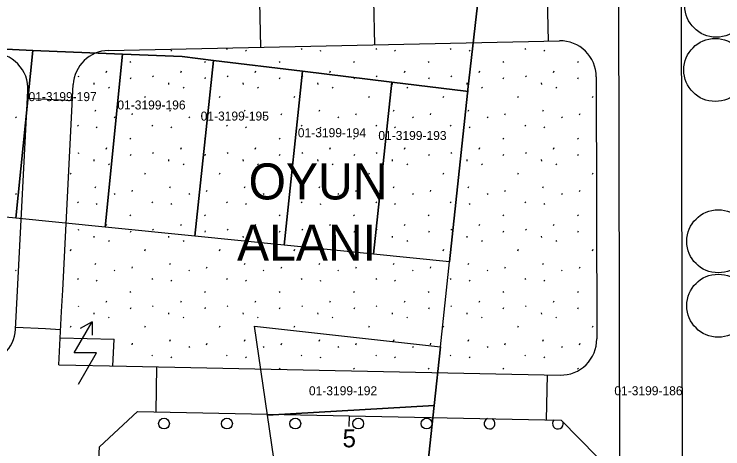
# Model space of a CAD drawing. Extents: x 419396 to 421519, y 4453567 to 4456767.
# Drawn here: x 420471.1 to 420549.9, y 4454570.9 to 4454619.2 of the extents above; entities that cross this region are included whole.
import ezdxf

# ---------------------------------------------------------------- set-up
doc = ezdxf.new("R2010")
doc.units = 0
for name, color, linetype in [('0_KADASTRO', 7, 'Continuous'), ('Level 20', 7, 'Continuous'), ('Level 28', 7, 'Continuous'), ('Level 29', 7, 'Continuous'), ('Level 33', 7, 'Continuous'), ('Level 41', 7, 'Continuous'), ('Level 54', 7, 'Continuous'), ('Level 55', 7, 'Continuous'), ('Level 57', 7, 'Continuous'), ('Level 61', 7, 'Continuous'), ('Level 62', 7, 'Continuous')]:
    doc.layers.add(name, color=color, linetype=linetype)

msp = doc.modelspace()

# ---------------------------------------------------------------- linework, layer by layer
at = {"layer": '0_KADASTRO'}
for points in [[(420411.106, 4454610.555), (420417.99, 4454723.39), (420418.06, 4454727.12), (420520.79, 4454737.14), (420523.08, 4454624.123), (420522.64, 4454620.22), (420521.583, 4454610.83), (420521.558, 4454610.634), (420521.36, 4454610.658), (420513.123, 4454611.658), (420503.201, 4454612.866), (420493.288, 4454614.075), (420489.81, 4454614.5), (420483.17, 4454614.78), (420473.19, 4454615.195), (420469.384, 4454615.353), (420447.99, 4454608.07), (420428.468, 4454594.055), (420413.06, 4454586.21), (420411.13, 4454609.71)], [(420515.046, 4454549.714), (420515.807, 4454556.873), (420516.899, 4454567.106), (420517.826, 4454575.752), (420518.521, 4454582.262), (420519.54, 4454591.714), (420521.536, 4454610.43), (420521.558, 4454610.634), (420521.583, 4454610.83), (420522.64, 4454620.22), (420523.08, 4454624.123), (420581.08, 4454632.15), (420580.07, 4454615.58), (420569.14, 4454565.51), (420569.77, 4454541.42), (420572.69, 4454525.26), (420529.64, 4454525.09), (420525.79, 4454524.02), (420524.53, 4454527.02), (420520.228, 4454537.319), (420516.246, 4454546.834)], [(420461.37, 4454597.533), (420462.84, 4454612.64), (420469.384, 4454615.353), (420473.19, 4454615.195), (420471.314, 4454596.544)], [(420471.314, 4454596.544), (420473.19, 4454615.195), (420483.17, 4454614.78), (420481.249, 4454595.545)], [(420481.249, 4454595.545), (420483.17, 4454614.78), (420489.81, 4454614.5), (420493.288, 4454614.075), (420491.194, 4454594.546)], [(420491.194, 4454594.546), (420493.288, 4454614.075), (420503.201, 4454612.866), (420501.138, 4454593.557)], [(420501.138, 4454593.557), (420503.201, 4454612.866), (420513.123, 4454611.658), (420511.083, 4454592.558)], [(420511.083, 4454592.558), (420513.123, 4454611.658), (420521.36, 4454610.658), (420521.558, 4454610.634), (420521.536, 4454610.43), (420519.54, 4454591.714)], [(420497.855, 4454584.548), (420518.521, 4454582.262), (420517.826, 4454575.752), (420499.295, 4454574.659)], [(420499.295, 4454574.659), (420517.826, 4454575.752), (420516.899, 4454567.106), (420500.744, 4454564.77)]]:
    msp.add_lwpolyline(points, close=True, dxfattribs=at)
at = {"layer": 'Level 20'}
msp.add_line((420508.359, 4454574.599), (420508.335, 4454573.4), dxfattribs=at)
at = {"layer": 'Level 28'}
for p, q in [((420530.525, 4454616.225), (420530.418, 4454621.224)), ((420498.388, 4454620.541), (420498.495, 4454615.542)), ((420511.084, 4454620.812), (420511.191, 4454615.813)), ((420481.608, 4454615.182), (420531.757, 4454616.251)), ((420535.842, 4454612.262), (420535.909, 4454583.133)), ((420476.516, 4454588.55), (420477.699, 4454611.39)), ((420471.507, 4454588.489), (420472.656, 4454610.699)), ((420472.615, 4454609.893), (420477.608, 4454609.634)), ((420471.286, 4454584.224), (420471.507, 4454588.489)), ((420476.393, 4454586.171), (420476.516, 4454588.55)), ((420476.516, 4454588.55), (420476.516, 4454588.55)), ((420476.087, 4454580.252), (420476.393, 4454586.171)), ((420476.393, 4454586.171), (420476.393, 4454586.171)), ((420471.297, 4454584.451), (420474.593, 4454584.281)), ((420474.593, 4454584.281), (420474.593, 4454584.281)), ((420474.593, 4454584.281), (420476.291, 4454584.193)), ((420476.087, 4454580.252), (420483.626, 4454580.1)), ((420483.626, 4454580.1), (420531.829, 4454579.125)), ((420486.9, 4454575.033), (420487.001, 4454580.032)), ((420530.317, 4454574.154), (420530.418, 4454579.153))]:
    msp.add_line(p, q, dxfattribs=at)
for centre, start, end in [((420531.842, 4454612.252), 0.13291, 91.22124), ((420481.693, 4454611.183), 91.22124, 177.03634), ((420468.662, 4454610.905), 357.03634, 91.22124), ((420467.291, 4454584.431), 268.8411, 357.03634), ((420531.909, 4454583.124), 268.8411, 0.13291)]:
    msp.add_arc(centre, 4, start, end, dxfattribs=at)
at = {"layer": 'Level 29'}
for p, q in [((420480.623, 4454571.161), (420484.829, 4454575.075)), ((420484.829, 4454575.075), (420531.931, 4454574.122)), ((420531.931, 4454574.122), (420535.94, 4454570.041)), ((420478.347, 4454527.194), (420480.623, 4454571.161))]:
    msp.add_line(p, q, dxfattribs=at)
at = {"layer": 'Level 33'}
for centre in [(420487.783, 4454573.735), (420494.783, 4454573.735), (420502.383, 4454573.735), (420509.383, 4454573.735), (420516.983, 4454573.735)]:
    msp.add_circle(centre, 0.6, dxfattribs=at)
for centre, start, end in [((420523.983, 4454573.735), 112.86595, 64.81587), ((420531.583, 4454573.735), 137.75884, 14.62376)]:
    msp.add_arc(centre, 0.6, start, end, dxfattribs=at)
at = {"layer": 'Level 41'}
for p, q in [((420532.059, 4454616.228), (420532.068, 4454616.216)), ((420486.517, 4454615.288), (420486.518, 4454615.286)), ((420488.546, 4454615.201), (420488.617, 4454615.094)), ((420494.74, 4454615.393), (420494.811, 4454615.286)), ((420496.839, 4454615.201), (420496.91, 4454615.094)), ((420503.033, 4454615.393), (420503.104, 4454615.286)), ((420505.132, 4454615.201), (420505.203, 4454615.094)), ((420511.326, 4454615.393), (420511.397, 4454615.286)), ((420513.425, 4454615.201), (420513.496, 4454615.094)), ((420519.619, 4454615.393), (420519.69, 4454615.286)), ((420521.718, 4454615.201), (420521.789, 4454615.094)), ((420527.912, 4454615.393), (420527.983, 4454615.286)), ((420530.011, 4454615.201), (420530.082, 4454615.094)), ((420483.991, 4454613.94), (420484.062, 4454613.833)), ((420492.284, 4454613.94), (420492.355, 4454613.833)), ((420500.577, 4454613.94), (420500.648, 4454613.833)), ((420508.87, 4454613.94), (420508.941, 4454613.833)), ((420517.163, 4454613.94), (420517.234, 4454613.833)), ((420525.456, 4454613.94), (420525.527, 4454613.833)), ((420533.749, 4454613.94), (420533.82, 4454613.833)), ((420481.35, 4454612.747), (420481.421, 4454612.906)), ((420489.643, 4454612.747), (420489.714, 4454612.906)), ((420497.936, 4454612.747), (420498.007, 4454612.906)), ((420506.229, 4454612.747), (420506.3, 4454612.906)), ((420514.522, 4454612.747), (420514.593, 4454612.906)), ((420522.815, 4454612.747), (420522.886, 4454612.906)), ((420531.108, 4454612.747), (420531.179, 4454612.906)), ((420478.221, 4454612.363), (420478.292, 4454612.256)), ((420484.049, 4454612.018), (420484.121, 4454612.178)), ((420486.514, 4454612.363), (420486.585, 4454612.256)), ((420492.342, 4454612.018), (420492.414, 4454612.178)), ((420494.807, 4454612.363), (420494.878, 4454612.256)), ((420500.635, 4454612.018), (420500.707, 4454612.178)), ((420503.1, 4454612.363), (420503.171, 4454612.256)), ((420508.928, 4454612.018), (420509, 4454612.178)), ((420511.393, 4454612.363), (420511.464, 4454612.256)), ((420517.221, 4454612.018), (420517.293, 4454612.178)), ((420519.686, 4454612.363), (420519.757, 4454612.256)), ((420525.514, 4454612.018), (420525.586, 4454612.178)), ((420527.979, 4454612.363), (420528.05, 4454612.256)), ((420533.807, 4454612.018), (420533.879, 4454612.178)), ((420479.979, 4454611.572), (420479.997, 4454611.412)), ((420481.609, 4454611.102), (420481.679, 4454610.995)), ((420488.272, 4454611.572), (420488.29, 4454611.412)), ((420489.902, 4454611.102), (420489.972, 4454610.995)), ((420496.565, 4454611.572), (420496.583, 4454611.412)), ((420498.195, 4454611.102), (420498.265, 4454610.995)), ((420504.858, 4454611.572), (420504.876, 4454611.412)), ((420506.488, 4454611.102), (420506.558, 4454610.995)), ((420513.151, 4454611.572), (420513.169, 4454611.412)), ((420514.781, 4454611.102), (420514.851, 4454610.995)), ((420521.444, 4454611.572), (420521.462, 4454611.412)), ((420523.074, 4454611.102), (420523.144, 4454610.995)), ((420529.737, 4454611.572), (420529.755, 4454611.412)), ((420531.367, 4454611.102), (420531.437, 4454610.995)), ((420485.665, 4454609.958), (420485.737, 4454610.118)), ((420493.958, 4454609.958), (420494.03, 4454610.118)), ((420502.251, 4454609.958), (420502.323, 4454610.118)), ((420510.544, 4454609.958), (420510.616, 4454610.118)), ((420518.837, 4454609.958), (420518.909, 4454610.118)), ((420527.13, 4454609.958), (420527.202, 4454610.118)), ((420535.423, 4454609.958), (420535.495, 4454610.118)), ((420480.144, 4454608.428), (420480.214, 4454608.588)), ((420484.227, 4454608.02), (420484.298, 4454608.18)), ((420488.437, 4454608.428), (420488.507, 4454608.588)), ((420492.52, 4454608.02), (420492.591, 4454608.18)), ((420496.73, 4454608.428), (420496.8, 4454608.588)), ((420500.813, 4454608.02), (420500.884, 4454608.18)), ((420505.023, 4454608.428), (420505.093, 4454608.588)), ((420509.106, 4454608.02), (420509.177, 4454608.18)), ((420513.316, 4454608.428), (420513.386, 4454608.588)), ((420517.399, 4454608.02), (420517.47, 4454608.18)), ((420521.609, 4454608.428), (420521.679, 4454608.588)), ((420525.692, 4454608.02), (420525.763, 4454608.18)), ((420529.902, 4454608.428), (420529.972, 4454608.588)), ((420533.985, 4454608.02), (420534.056, 4454608.18)), ((420471.263, 4454607.812), (420471.334, 4454607.706)), ((420482.239, 4454607.812), (420482.31, 4454607.706)), ((420490.532, 4454607.812), (420490.603, 4454607.706)), ((420498.825, 4454607.812), (420498.896, 4454607.706)), ((420507.118, 4454607.812), (420507.189, 4454607.706)), ((420515.411, 4454607.812), (420515.482, 4454607.706)), ((420523.704, 4454607.812), (420523.775, 4454607.706)), ((420531.997, 4454607.812), (420532.068, 4454607.706)), ((420478.154, 4454606.883), (420478.225, 4454606.776)), ((420480.253, 4454606.691), (420480.324, 4454606.584)), ((420486.447, 4454606.883), (420486.518, 4454606.776)), ((420488.546, 4454606.691), (420488.617, 4454606.584)), ((420494.74, 4454606.883), (420494.811, 4454606.776)), ((420496.839, 4454606.691), (420496.91, 4454606.584)), ((420503.033, 4454606.883), (420503.104, 4454606.776)), ((420505.132, 4454606.691), (420505.203, 4454606.584)), ((420511.326, 4454606.883), (420511.397, 4454606.776)), ((420513.425, 4454606.691), (420513.496, 4454606.584)), ((420519.619, 4454606.883), (420519.69, 4454606.776)), ((420521.718, 4454606.691), (420521.789, 4454606.584)), ((420527.912, 4454606.883), (420527.983, 4454606.776)), ((420530.011, 4454606.691), (420530.082, 4454606.584)), ((420483.991, 4454605.43), (420484.062, 4454605.323)), ((420492.284, 4454605.43), (420492.355, 4454605.323)), ((420500.577, 4454605.43), (420500.648, 4454605.323)), ((420508.87, 4454605.43), (420508.941, 4454605.323)), ((420517.163, 4454605.43), (420517.234, 4454605.323)), ((420525.456, 4454605.43), (420525.527, 4454605.323)), ((420533.749, 4454605.43), (420533.82, 4454605.323)), ((420481.35, 4454604.237), (420481.421, 4454604.396)), ((420489.643, 4454604.237), (420489.714, 4454604.396)), ((420497.936, 4454604.237), (420498.007, 4454604.396)), ((420506.229, 4454604.237), (420506.3, 4454604.396)), ((420514.522, 4454604.237), (420514.593, 4454604.396)), ((420522.815, 4454604.237), (420522.886, 4454604.396)), ((420531.108, 4454604.237), (420531.179, 4454604.396)), ((420478.221, 4454603.853), (420478.292, 4454603.746)), ((420484.049, 4454603.508), (420484.121, 4454603.668)), ((420486.514, 4454603.853), (420486.585, 4454603.746)), ((420492.342, 4454603.508), (420492.414, 4454603.668)), ((420494.807, 4454603.853), (420494.878, 4454603.746)), ((420500.635, 4454603.508), (420500.707, 4454603.668)), ((420503.1, 4454603.853), (420503.171, 4454603.746)), ((420508.928, 4454603.508), (420509, 4454603.668)), ((420511.393, 4454603.853), (420511.464, 4454603.746)), ((420517.221, 4454603.508), (420517.293, 4454603.668)), ((420519.686, 4454603.853), (420519.757, 4454603.746)), ((420525.514, 4454603.508), (420525.586, 4454603.668)), ((420527.979, 4454603.853), (420528.05, 4454603.746)), ((420533.807, 4454603.508), (420533.879, 4454603.668)), ((420479.979, 4454603.062), (420479.997, 4454602.902)), ((420481.609, 4454602.592), (420481.679, 4454602.485)), ((420488.272, 4454603.062), (420488.29, 4454602.902)), ((420489.902, 4454602.592), (420489.972, 4454602.485)), ((420496.565, 4454603.062), (420496.583, 4454602.902)), ((420498.195, 4454602.592), (420498.265, 4454602.485)), ((420504.858, 4454603.062), (420504.876, 4454602.902)), ((420506.488, 4454602.592), (420506.558, 4454602.485)), ((420513.151, 4454603.062), (420513.169, 4454602.902)), ((420514.781, 4454602.592), (420514.851, 4454602.485)), ((420521.444, 4454603.062), (420521.462, 4454602.902)), ((420523.074, 4454602.592), (420523.144, 4454602.485)), ((420529.737, 4454603.062), (420529.755, 4454602.902)), ((420531.367, 4454602.592), (420531.437, 4454602.485)), ((420477.372, 4454601.448), (420477.444, 4454601.608)), ((420485.665, 4454601.448), (420485.737, 4454601.608)), ((420493.958, 4454601.448), (420494.03, 4454601.608)), ((420502.251, 4454601.448), (420502.323, 4454601.608)), ((420510.544, 4454601.448), (420510.616, 4454601.608)), ((420518.837, 4454601.448), (420518.909, 4454601.608)), ((420527.13, 4454601.448), (420527.202, 4454601.608)), ((420535.423, 4454601.448), (420535.495, 4454601.608)), ((420480.144, 4454599.918), (420480.214, 4454600.078)), ((420488.437, 4454599.918), (420488.507, 4454600.078)), ((420496.73, 4454599.918), (420496.8, 4454600.078)), ((420505.023, 4454599.918), (420505.093, 4454600.078)), ((420513.316, 4454599.918), (420513.386, 4454600.078)), ((420521.609, 4454599.918), (420521.679, 4454600.078)), ((420529.902, 4454599.918), (420529.972, 4454600.078)), ((420471.263, 4454599.302), (420471.334, 4454599.196)), ((420482.239, 4454599.302), (420482.31, 4454599.196)), ((420484.227, 4454599.51), (420484.298, 4454599.67)), ((420490.532, 4454599.302), (420490.603, 4454599.196)), ((420492.52, 4454599.51), (420492.591, 4454599.67)), ((420498.825, 4454599.302), (420498.896, 4454599.196)), ((420500.813, 4454599.51), (420500.884, 4454599.67)), ((420507.118, 4454599.302), (420507.189, 4454599.196)), ((420509.106, 4454599.51), (420509.177, 4454599.67)), ((420515.411, 4454599.302), (420515.482, 4454599.196)), ((420517.399, 4454599.51), (420517.47, 4454599.67)), ((420523.704, 4454599.302), (420523.775, 4454599.196)), ((420525.692, 4454599.51), (420525.763, 4454599.67)), ((420531.997, 4454599.302), (420532.068, 4454599.196)), ((420533.985, 4454599.51), (420534.056, 4454599.67)), ((420478.154, 4454598.373), (420478.225, 4454598.266)), ((420486.447, 4454598.373), (420486.518, 4454598.266)), ((420494.74, 4454598.373), (420494.811, 4454598.266)), ((420503.033, 4454598.373), (420503.104, 4454598.266)), ((420511.326, 4454598.373), (420511.397, 4454598.266)), ((420519.619, 4454598.373), (420519.69, 4454598.266)), ((420527.912, 4454598.373), (420527.983, 4454598.266)), ((420480.253, 4454598.181), (420480.324, 4454598.074)), ((420488.546, 4454598.181), (420488.617, 4454598.074)), ((420496.839, 4454598.181), (420496.91, 4454598.074)), ((420505.132, 4454598.181), (420505.203, 4454598.074)), ((420513.425, 4454598.181), (420513.496, 4454598.074)), ((420521.718, 4454598.181), (420521.789, 4454598.074)), ((420530.011, 4454598.181), (420530.082, 4454598.074)), ((420483.991, 4454596.92), (420484.062, 4454596.813)), ((420492.284, 4454596.92), (420492.355, 4454596.813)), ((420500.577, 4454596.92), (420500.648, 4454596.813)), ((420508.87, 4454596.92), (420508.941, 4454596.813)), ((420517.163, 4454596.92), (420517.234, 4454596.813)), ((420525.456, 4454596.92), (420525.527, 4454596.813)), ((420533.749, 4454596.92), (420533.82, 4454596.813)), ((420478.221, 4454595.343), (420478.292, 4454595.236)), ((420481.35, 4454595.727), (420481.421, 4454595.886)), ((420486.514, 4454595.343), (420486.585, 4454595.236)), ((420489.643, 4454595.727), (420489.714, 4454595.886)), ((420494.807, 4454595.343), (420494.878, 4454595.236)), ((420497.936, 4454595.727), (420498.007, 4454595.886)), ((420503.1, 4454595.343), (420503.171, 4454595.236)), ((420506.229, 4454595.727), (420506.3, 4454595.886)), ((420511.393, 4454595.343), (420511.464, 4454595.236)), ((420514.522, 4454595.727), (420514.593, 4454595.886)), ((420519.686, 4454595.343), (420519.757, 4454595.236)), ((420522.815, 4454595.727), (420522.886, 4454595.886)), ((420527.979, 4454595.343), (420528.05, 4454595.236)), ((420531.108, 4454595.727), (420531.179, 4454595.886)), ((420479.979, 4454594.552), (420479.997, 4454594.392)), ((420484.049, 4454594.998), (420484.121, 4454595.158)), ((420488.272, 4454594.552), (420488.29, 4454594.392)), ((420492.342, 4454594.998), (420492.414, 4454595.158)), ((420496.565, 4454594.552), (420496.583, 4454594.392)), ((420500.635, 4454594.998), (420500.707, 4454595.158)), ((420504.858, 4454594.552), (420504.876, 4454594.392)), ((420508.928, 4454594.998), (420509, 4454595.158)), ((420513.151, 4454594.552), (420513.169, 4454594.392)), ((420517.221, 4454594.998), (420517.293, 4454595.158)), ((420521.444, 4454594.552), (420521.462, 4454594.392)), ((420525.514, 4454594.998), (420525.586, 4454595.158)), ((420529.737, 4454594.552), (420529.755, 4454594.392)), ((420533.807, 4454594.998), (420533.879, 4454595.158)), ((420481.609, 4454594.082), (420481.679, 4454593.975)), ((420489.902, 4454594.082), (420489.972, 4454593.975)), ((420498.195, 4454594.082), (420498.265, 4454593.975)), ((420506.488, 4454594.082), (420506.558, 4454593.975)), ((420514.781, 4454594.082), (420514.851, 4454593.975)), ((420523.074, 4454594.082), (420523.144, 4454593.975)), ((420531.367, 4454594.082), (420531.437, 4454593.975)), ((420477.372, 4454592.938), (420477.444, 4454593.098)), ((420485.665, 4454592.938), (420485.737, 4454593.098)), ((420493.958, 4454592.938), (420494.03, 4454593.098)), ((420502.251, 4454592.938), (420502.323, 4454593.098)), ((420510.544, 4454592.938), (420510.616, 4454593.098)), ((420518.837, 4454592.938), (420518.909, 4454593.098)), ((420527.13, 4454592.938), (420527.202, 4454593.098)), ((420535.423, 4454592.938), (420535.495, 4454593.098)), ((420480.144, 4454591.408), (420480.214, 4454591.568)), ((420488.437, 4454591.408), (420488.507, 4454591.568)), ((420496.73, 4454591.408), (420496.8, 4454591.568)), ((420505.023, 4454591.408), (420505.093, 4454591.568)), ((420513.316, 4454591.408), (420513.386, 4454591.568)), ((420521.609, 4454591.408), (420521.679, 4454591.568)), ((420529.902, 4454591.408), (420529.972, 4454591.568)), ((420471.263, 4454590.792), (420471.334, 4454590.686)), ((420482.239, 4454590.792), (420482.31, 4454590.686)), ((420484.227, 4454591), (420484.298, 4454591.16)), ((420490.532, 4454590.792), (420490.603, 4454590.686)), ((420492.52, 4454591), (420492.591, 4454591.16)), ((420498.825, 4454590.792), (420498.896, 4454590.686)), ((420500.813, 4454591), (420500.884, 4454591.16)), ((420507.118, 4454590.792), (420507.189, 4454590.686)), ((420509.106, 4454591), (420509.177, 4454591.16)), ((420515.411, 4454590.792), (420515.482, 4454590.686)), ((420517.399, 4454591), (420517.47, 4454591.16)), ((420523.704, 4454590.792), (420523.775, 4454590.686)), ((420525.692, 4454591), (420525.763, 4454591.16)), ((420531.997, 4454590.792), (420532.068, 4454590.686)), ((420533.985, 4454591), (420534.056, 4454591.16)), ((420478.154, 4454589.863), (420478.225, 4454589.756)), ((420486.447, 4454589.863), (420486.518, 4454589.756)), ((420494.74, 4454589.863), (420494.811, 4454589.756)), ((420503.033, 4454589.863), (420503.104, 4454589.756)), ((420511.326, 4454589.863), (420511.397, 4454589.756)), ((420519.619, 4454589.863), (420519.69, 4454589.756)), ((420527.912, 4454589.863), (420527.983, 4454589.756)), ((420480.253, 4454589.671), (420480.324, 4454589.564)), ((420488.546, 4454589.671), (420488.617, 4454589.564)), ((420496.839, 4454589.671), (420496.91, 4454589.564)), ((420505.132, 4454589.671), (420505.203, 4454589.564)), ((420513.425, 4454589.671), (420513.496, 4454589.564)), ((420521.718, 4454589.671), (420521.789, 4454589.564)), ((420530.011, 4454589.671), (420530.082, 4454589.564)), ((420483.991, 4454588.41), (420484.062, 4454588.303)), ((420492.284, 4454588.41), (420492.355, 4454588.303)), ((420500.577, 4454588.41), (420500.648, 4454588.303)), ((420508.87, 4454588.41), (420508.941, 4454588.303)), ((420517.163, 4454588.41), (420517.234, 4454588.303)), ((420525.456, 4454588.41), (420525.527, 4454588.303)), ((420533.749, 4454588.41), (420533.82, 4454588.303)), ((420481.35, 4454587.217), (420481.421, 4454587.376)), ((420489.643, 4454587.217), (420489.714, 4454587.376)), ((420497.936, 4454587.217), (420498.007, 4454587.376)), ((420506.229, 4454587.217), (420506.3, 4454587.376)), ((420514.522, 4454587.217), (420514.593, 4454587.376)), ((420522.815, 4454587.217), (420522.886, 4454587.376)), ((420531.108, 4454587.217), (420531.179, 4454587.376)), ((420478.221, 4454586.833), (420478.292, 4454586.726)), ((420484.049, 4454586.488), (420484.121, 4454586.648)), ((420486.514, 4454586.833), (420486.585, 4454586.726)), ((420492.342, 4454586.488), (420492.414, 4454586.648)), ((420494.807, 4454586.833), (420494.878, 4454586.726)), ((420500.635, 4454586.488), (420500.707, 4454586.648)), ((420503.1, 4454586.833), (420503.171, 4454586.726)), ((420508.928, 4454586.488), (420509, 4454586.648)), ((420511.393, 4454586.833), (420511.464, 4454586.726)), ((420517.221, 4454586.488), (420517.293, 4454586.648)), ((420519.686, 4454586.833), (420519.757, 4454586.726)), ((420525.514, 4454586.488), (420525.586, 4454586.648)), ((420527.979, 4454586.833), (420528.05, 4454586.726)), ((420533.807, 4454586.488), (420533.879, 4454586.648)), ((420479.979, 4454586.042), (420479.997, 4454585.882)), ((420488.272, 4454586.042), (420488.29, 4454585.882)), ((420496.565, 4454586.042), (420496.583, 4454585.882)), ((420504.858, 4454586.042), (420504.876, 4454585.882)), ((420513.151, 4454586.042), (420513.169, 4454585.882)), ((420521.444, 4454586.042), (420521.462, 4454585.882)), ((420529.737, 4454586.042), (420529.755, 4454585.882)), ((420481.609, 4454585.572), (420481.679, 4454585.465)), ((420489.902, 4454585.572), (420489.972, 4454585.465)), ((420498.195, 4454585.572), (420498.265, 4454585.465)), ((420506.488, 4454585.572), (420506.558, 4454585.465)), ((420514.781, 4454585.572), (420514.851, 4454585.465)), ((420523.074, 4454585.572), (420523.144, 4454585.465)), ((420531.367, 4454585.572), (420531.437, 4454585.465)), ((420477.372, 4454584.428), (420477.444, 4454584.588)), ((420485.665, 4454584.428), (420485.737, 4454584.588)), ((420493.958, 4454584.428), (420494.03, 4454584.588)), ((420502.251, 4454584.428), (420502.323, 4454584.588)), ((420510.544, 4454584.428), (420510.616, 4454584.588)), ((420518.837, 4454584.428), (420518.909, 4454584.588)), ((420527.13, 4454584.428), (420527.202, 4454584.588)), ((420535.423, 4454584.428), (420535.495, 4454584.588)), ((420484.227, 4454582.49), (420484.298, 4454582.65)), ((420488.437, 4454582.898), (420488.507, 4454583.058)), ((420492.52, 4454582.49), (420492.591, 4454582.65)), ((420496.73, 4454582.898), (420496.8, 4454583.058)), ((420500.813, 4454582.49), (420500.884, 4454582.65)), ((420505.023, 4454582.898), (420505.093, 4454583.058)), ((420509.106, 4454582.49), (420509.177, 4454582.65)), ((420513.316, 4454582.898), (420513.386, 4454583.058)), ((420517.399, 4454582.49), (420517.47, 4454582.65)), ((420521.609, 4454582.898), (420521.679, 4454583.058)), ((420525.692, 4454582.49), (420525.763, 4454582.65)), ((420529.902, 4454582.898), (420529.972, 4454583.058)), ((420533.985, 4454582.49), (420534.056, 4454582.65)), ((420490.532, 4454582.282), (420490.603, 4454582.176)), ((420498.825, 4454582.282), (420498.896, 4454582.176)), ((420507.118, 4454582.282), (420507.189, 4454582.176)), ((420515.411, 4454582.282), (420515.482, 4454582.176)), ((420523.704, 4454582.282), (420523.775, 4454582.176)), ((420531.997, 4454582.282), (420532.068, 4454582.176)), ((420486.447, 4454581.353), (420486.518, 4454581.246)), ((420488.546, 4454581.161), (420488.617, 4454581.054)), ((420494.74, 4454581.353), (420494.811, 4454581.246)), ((420496.839, 4454581.161), (420496.91, 4454581.054)), ((420503.033, 4454581.353), (420503.104, 4454581.246)), ((420505.132, 4454581.161), (420505.203, 4454581.054)), ((420511.326, 4454581.353), (420511.397, 4454581.246)), ((420513.425, 4454581.161), (420513.496, 4454581.054)), ((420519.619, 4454581.353), (420519.69, 4454581.246)), ((420521.718, 4454581.161), (420521.789, 4454581.054)), ((420527.912, 4454581.353), (420527.983, 4454581.246)), ((420530.011, 4454581.161), (420530.082, 4454581.054)), ((420500.577, 4454579.9), (420500.648, 4454579.793)), ((420508.87, 4454579.9), (420508.941, 4454579.793)), ((420517.163, 4454579.9), (420517.234, 4454579.793)), ((420525.456, 4454579.9), (420525.527, 4454579.793)), ((420533.749, 4454579.9), (420533.82, 4454579.793))]:
    msp.add_line(p, q, dxfattribs=at)
at = {"layer": 'Level 54'}
for p, q in [((420477.777, 4454581.582), (420479.777, 4454585.046)), ((420480.277, 4454581.582), (420477.777, 4454581.582)), ((420478.278, 4454578.119), (420480.277, 4454581.582))]:
    msp.add_line(p, q, dxfattribs=at)
for points in [[(420479.777, 4454585.046), (420478.478, 4454584.296)], [(420479.777, 4454585.046), (420479.777, 4454583.546)]]:
    msp.add_lwpolyline(points, dxfattribs=at)
at = {"layer": 'Level 55'}
for centre in [(420549.196, 4454620.16), (420549.083, 4454613.016), (420549.413, 4454593.982), (420549.413, 4454586.831)]:
    msp.add_circle(centre, 3.5, dxfattribs=at)
at = {"layer": 'Level 57'}
for p in [(420476.242, 4454583.251), (420482.087, 4454580.131)]:
    msp.add_line(p, (420482.242, 4454583.13), dxfattribs=at)
at = {"layer": 'Level 62'}
for p, q in [((420545.535, 4454529.201), (420545.071, 4454729.082)), ((420538.074, 4454727.607), (420538.541, 4454526.537))]:
    msp.add_line(p, q, dxfattribs=at)

# ---------------------------------------------------------------- texts
at = {"layer": '0_KADASTRO'}
for s, p in [('01-3199-197', (420472.718, 4454609.553)), ('01-3199-196', (420482.597, 4454608.628)), ('01-3199-195', (420491.859, 4454607.395)), ('01-3199-194', (420502.664, 4454605.546)), ('01-3199-193', (420511.617, 4454605.238)), ('01-3199-192', (420503.899, 4454576.881)), ('01-3199-186', (420537.858, 4454576.881))]:
    msp.add_text(s, height=1, dxfattribs=at).set_placement(p)
at = {"layer": 'Level 20'}
msp.add_text('5', height=2, rotation=358.84109, dxfattribs=at).set_placement((420507.622, 4454571.113))
at = {"layer": 'Level 61'}
for s, p in [('OYUN', (420497.185, 4454598.635)), ('ALANI', (420495.902, 4454591.829))]:
    msp.add_text(s, height=4, dxfattribs=at).set_placement(p)

doc.saveas('drawing.dxf')
